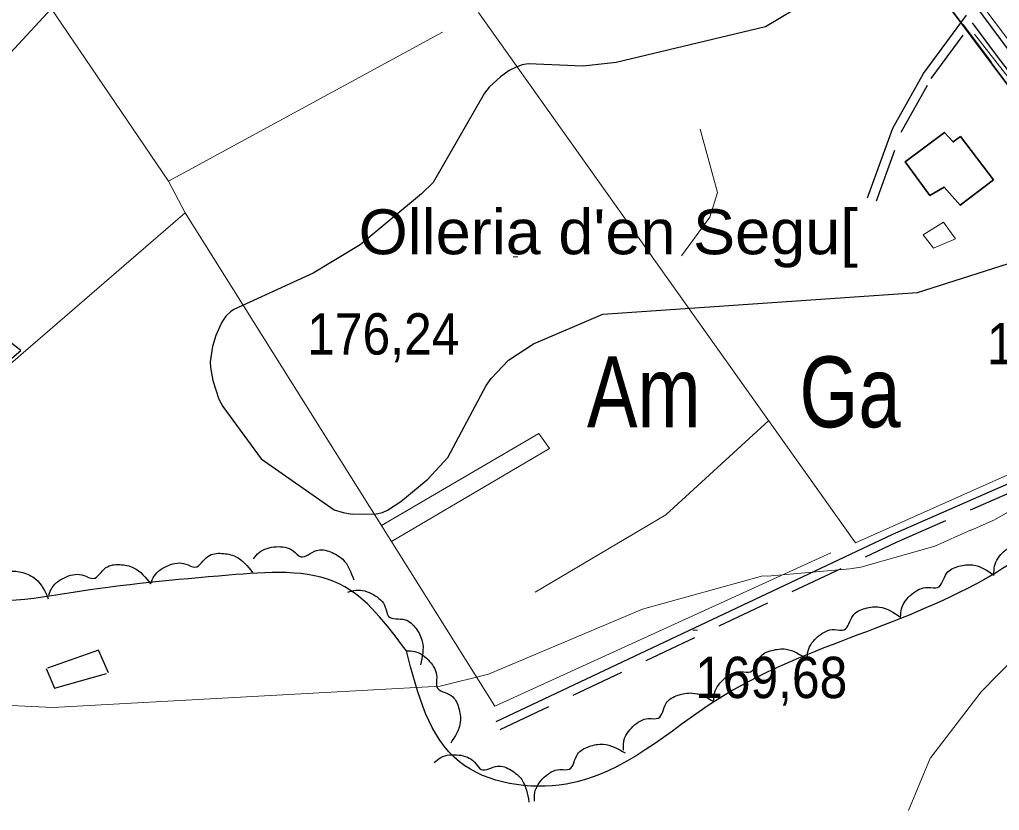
# Model space of a CAD drawing. Extents: x 480269 to 484877, y 4383588 to 4386804.
# Drawn here: x 482052.3 to 482259.6, y 4385605.8 to 4385773.1 of the extents above; entities that cross this region are included whole.
import ezdxf
from ezdxf.enums import TextEntityAlignment as Align

# ---------------------------------------------------------------- set-up
doc = ezdxf.new("R2010")
doc.units = 0
doc.header["$LTSCALE"] = 3.8
doc.linetypes.add('MEDIUM_DASHED', pattern=[4.5, 3, -1.5])
for name, color, linetype, lineweight in [('21', 7, 'Continuous', 25), ('27', 7, 'Continuous', 25), ('34', 7, 'Continuous', 35), ('38', 7, 'Continuous', 25), ('47', 7, 'Continuous', 35), ('48', 7, 'MEDIUM_DASHED', 25), ('51', 7, 'Continuous', 13), ('7', 7, 'Continuous', 13), ('8', 7, 'Continuous', 25), ('9', 7, 'Continuous', 13)]:
    doc.layers.add(name, color=color, linetype=linetype, lineweight=lineweight)
doc.layers.add('31', color=7, linetype='Continuous')
doc.layers.add('5', color=7, linetype='Continuous')

msp = doc.modelspace()

# ---------------------------------------------------------------- linework, layer by layer
at = {"layer": '21'}
msp.add_lwpolyline([(482044.36, 4385701.2), (482046.63, 4385698.12), (482052.53, 4385703.11), (482049.05, 4385705.87)], close=True, dxfattribs=at)
at = {"layer": '27'}
for points in [[(482928.34, 4385924.89), (482922.57, 4385923.15), (482885.78, 4385895.73), (482830.19, 4385870.67), (482783.99, 4385846.38), (482748.76, 4385821.32), (482700.22, 4385785.28), (482658.72, 4385739.07), (482615.66, 4385695.2), (482579.64, 4385663.09), (482560.07, 4385645.07), (482539.71, 4385649.77), (482459.85, 4385672.49), (482360.42, 4385703.82), (482306.4, 4385727.32), (482257.85, 4385789.2), (482191.3, 4385880.85), (482166.25, 4385912.96), (482169.38, 4385923.15), (482197.57, 4385932.55), (482218.71, 4385942.73), (482235.93, 4385961.53), (482260.99, 4385957.61), (482288.39, 4385973.28), (482296.22, 4385991.3), (482306.4, 4385999.91), (482324.4, 4386001.48), (482354.16, 4385995.21), (482372.16, 4385973.28), (482387.82, 4385970.15), (482414.44, 4385988.16), (482434.02, 4385990.51), (482466.12, 4385956.05), (482473.95, 4385954.08)], [(482134.14, 4385639.56), (482145.42, 4385616.05), (482167.98, 4385611.34), (482199.94, 4385629.21), (482256.34, 4385654.6), (482299.58, 4385676.23), (482309.92, 4385675.29), (482324.96, 4385660.25), (482353.16, 4385626.39), (482366.32, 4385607.58), (482355.04, 4385597.24), (482347.52, 4385585.01), (482347.52, 4385561.5), (482356.92, 4385553.04), (482382.29, 4385553.98), (482400.15, 4385553.98), (482414.25, 4385537.05), (482418.01, 4385522), (482407.67, 4385512.6), (482383.23, 4385513.54), (482370.08, 4385507.9), (482358.8, 4385494.73), (482359.74, 4385477.8), (482342.82, 4385454.29), (482257.28, 4385376.24), (482191.48, 4385317.93), (482156.7, 4385290.66), (482136.02, 4385273.73), (482119.1, 4385272.79), (482113.46, 4385285.02), (482126.62, 4385312.29), (482143.54, 4385346.14), (482160.46, 4385378.12), (482156.7, 4385395.99), (482134.14, 4385407.27), (482113.46, 4385416.68), (482093.72, 4385412.91), (482087.14, 4385401.63), (482072.1, 4385398.81), (482050.48, 4385407.27), (482035.44, 4385408.21), (482021.34, 4385395.05), (482005.36, 4385398.81), (482011, 4385429.84), (482001.6, 4385476.86), (481971.52, 4385519.18), (481936.74, 4385563.38), (481930.16, 4385579.37), (481941.44, 4385597.24), (481940.5, 4385616.99), (481916.06, 4385648.96), (481908.54, 4385674.35), (481928.28, 4385695.98), (481936.74, 4385694.1), (481957.42, 4385664.01), (481967.76, 4385648.02), (481979.04, 4385640.5), (481992.2, 4385648.02), (482008.18, 4385667.77), (482022.28, 4385668.71), (482035.44, 4385653.66), (482062.7, 4385651.78), (482096.54, 4385655.54), (482120.04, 4385653.66), (482134.14, 4385639.56)], [(482258.48, 4385655.67), (482258.61, 4385657.44), (482260.66, 4385660.63), (482264.01, 4385662.18), (482266.06, 4385662.23), (482267.83, 4385665.31), (482270.35, 4385666.91), (482273.35, 4385667.31), (482277.91, 4385665.34)], [(482101.79, 4385659.03), (482102.99, 4385660.34), (482106.58, 4385661.57), (482110.16, 4385660.7), (482111.81, 4385659.47), (482115.11, 4385660.79), (482118.08, 4385660.47), (482120.67, 4385658.92), (482123.02, 4385654.56)], [(482080.03, 4385653.72), (482080.76, 4385655.34), (482083.79, 4385657.62), (482087.47, 4385657.92), (482089.41, 4385657.26), (482092.14, 4385659.54), (482095.06, 4385660.17), (482098.01, 4385659.5), (482101.61, 4385656.09)], [(482036.86, 4385653.47), (482037.96, 4385654.86), (482041.45, 4385656.35), (482045.09, 4385655.75), (482046.82, 4385654.64), (482050.02, 4385656.19), (482053, 4385656.09), (482055.7, 4385654.74), (482058.37, 4385650.56)], [(482058.47, 4385651.31), (482059.19, 4385652.93), (482062.22, 4385655.22), (482065.9, 4385655.52), (482067.84, 4385654.86), (482070.56, 4385657.15), (482073.48, 4385657.78), (482076.43, 4385657.12), (482080.04, 4385653.71)], [(482238.74, 4385646.67), (482238.93, 4385648.44), (482241.11, 4385651.55), (482244.51, 4385652.96), (482246.57, 4385652.93), (482248.46, 4385655.94), (482251.04, 4385657.44), (482254.05, 4385657.72), (482258.53, 4385655.57)], [(482121.76, 4385651.94), (482123.48, 4385652.38), (482127.16, 4385651.45), (482129.69, 4385648.76), (482130.39, 4385646.83), (482133.88, 4385646.13), (482136.19, 4385644.24), (482137.52, 4385641.53), (482137.1, 4385636.59)], [(482218.95, 4385637.76), (482219.14, 4385639.53), (482221.32, 4385642.64), (482224.73, 4385644.05), (482226.78, 4385644.02), (482228.67, 4385647.03), (482231.26, 4385648.53), (482234.27, 4385648.81), (482238.74, 4385646.66)], [(482199.16, 4385628.86), (482199.35, 4385630.62), (482201.53, 4385633.73), (482204.94, 4385635.15), (482206.99, 4385635.12), (482208.88, 4385638.13), (482211.47, 4385639.62), (482214.48, 4385639.9), (482218.95, 4385637.76)], [(482134.14, 4385639.56), (482135.91, 4385639.41), (482139.07, 4385637.31), (482140.57, 4385633.94), (482140.59, 4385631.88), (482143.64, 4385630.07), (482145.2, 4385627.52), (482145.55, 4385624.52), (482143.52, 4385619.99)], [(482180.08, 4385618.53), (482180.14, 4385620.3), (482182.1, 4385623.55), (482185.4, 4385625.21), (482187.45, 4385625.32), (482189.12, 4385628.46), (482191.6, 4385630.13), (482194.58, 4385630.62), (482199.19, 4385628.8)], [(482161.25, 4385607.76), (482161.32, 4385609.53), (482163.29, 4385612.78), (482166.6, 4385614.41), (482168.65, 4385614.52), (482170.34, 4385617.65), (482172.82, 4385619.3), (482175.81, 4385619.78), (482180.41, 4385617.94)], [(482140.04, 4385615.9), (482141.46, 4385616.96), (482145.21, 4385617.5), (482148.58, 4385615.98), (482149.96, 4385614.46), (482153.45, 4385615.14), (482156.31, 4385614.28), (482158.57, 4385612.28), (482160.07, 4385607.55)]]:
    msp.add_spline(points, degree=3, dxfattribs=at)
at = {"layer": '34'}
msp.add_line((482251.88, 4385772.09), (482257.87, 4385764.09), dxfattribs=at)
msp.add_lwpolyline([(481732.67, 4386453.74), (481770, 4386403), (482108, 4385964), (482722, 4385145)], dxfattribs=at)
at = {"layer": '38'}
for points in [[(481964.71, 4386161.53), (481984.04, 4386137.62), (482003.54, 4386111.27), (482025.11, 4386083.66), (482045.74, 4386055.24), (482069.87, 4386023.53), (482092.3, 4385993.28), (482108.78, 4385971.62), (482137.33, 4385933.4), (482160.69, 4385901.12), (482191.72, 4385858.66), (482221.47, 4385819.56), (482242.16, 4385792.86), (482263.36, 4385764.29), (482272.97, 4385751.53), (482292.17, 4385726.65), (482297.56, 4385719.51), (482298.68, 4385719.01), (482300.35, 4385718.99), (482305.15, 4385718.26), (482309.51, 4385716.64)], [(482231.76, 4385735.43), (482237.09, 4385750.13), (482243.56, 4385761.69), (482252.65, 4385774.08)], [(482253.87, 4385772.44), (482259.37, 4385765.04), (482270.86, 4385750.05), (482288.86, 4385726.29), (482295.69, 4385717.31), (482296.78, 4385716.83)], [(482153.18, 4385624.57), (482237.11, 4385664.26), (482310.39, 4385696.34), (482310.52, 4385696.96), (482309.92, 4385698.86), (482296.78, 4385716.83)]]:
    msp.add_lwpolyline(points, dxfattribs=at)
at = {"layer": '38', "linetype": 'MEDIUM_DASHED'}
for points in [[(482233.6, 4385734.76), (482238.88, 4385749.31), (482245.21, 4385760.63), (482253.87, 4385772.44)], [(482153.98, 4385622.88), (482237.89, 4385662.56), (482311.25, 4385694.68)]]:
    msp.add_lwpolyline(points, dxfattribs=at)
at = {"layer": '47'}
msp.add_lwpolyline([(482258.42, 4385739.23), (482251.37, 4385733.85), (482247.94, 4385737.68), (482244.93, 4385735.89), (482239.71, 4385743.03), (482248, 4385749.24), (482249.82, 4385747.25), (482251.38, 4385748.38)], close=True, dxfattribs=at)
at = {"layer": '47', "lineweight": 13}
msp.add_lwpolyline([(482250.35, 4385726.74), (482247.81, 4385730.24), (482243.51, 4385727.59), (482245.69, 4385724.76)], close=True, dxfattribs=at)
at = {"layer": '48'}
msp.add_lwpolyline([(482071.13, 4385634.87), (482068.97, 4385639.66), (482057.92, 4385635.81), (482059.7, 4385631.64)], close=True, dxfattribs=at)
at = {"layer": '51'}
msp.add_line((482083.8, 4385738.92), (482039.24, 4385804.6), dxfattribs=at)
for points in [[(482779.62, 4386098.45), (482742.85, 4386070.07), (482699.48, 4386036.34), (482644.98, 4385992.23), (482611.45, 4385965.76), (482554.45, 4385920.69), (482472.77, 4385856.39), (482299.35, 4385719.82), (482274.18, 4385752.03), (482255.92, 4385776.25), (482234.75, 4385804.89), (482209.61, 4385837.32), (482152.61, 4385914.04), (482157.42, 4385920.91)], [(482149.4, 4385774.65), (482229.21, 4385662.41), (482307.44, 4385697.3), (482307.88, 4385699.78), (482270.82, 4385749), (482254.38, 4385770.06)], [(482141.76, 4385770.45), (482083.8, 4385738.92), (482087.33, 4385732.24)], [(482196.28, 4385749.97), (482200.01, 4385736.56), (482198.39, 4385731.29), (482192.34, 4385723.17)], [(482029.1, 4385681.95), (482087.33, 4385732.24), (482152.87, 4385627.8), (482223.94, 4385660.26)], [(482161.37, 4385651.94), (482189.08, 4385668.34), (482210.83, 4385688.28)], [(482130.97, 4385662.71), (482164.45, 4385682.34), (482162.19, 4385685.56), (482128.86, 4385666.08)]]:
    msp.add_lwpolyline(points, dxfattribs=at)
at = {"layer": '7'}
for p, q in [((482156.74, 4385722.95), (482157.74, 4385722.95)), ((482194.74, 4385643.91), (482195.74, 4385643.91))]:
    msp.add_line(p, q, dxfattribs=at)
at = {"layer": '8'}
msp.add_lwpolyline([(482252.53, 4385796.92), (482210.17, 4385771.58), (482178.54, 4385764.06), (482171.56, 4385763.24), (482159.93, 4385763.77), (482158.63, 4385763.53), (482157.38, 4385763.09), (482155.91, 4385762.33), (482154.08, 4385761.05), (482151.66, 4385758.81), (482150.67, 4385757.58), (482139.8, 4385738.69), (482137.36, 4385736.23), (482124.34, 4385725.43), (482114.43, 4385719.44), (482097.64, 4385711.8), (482096.95, 4385711.3), (482095.97, 4385710.37), (482095.36, 4385709.55), (482095.02, 4385708.97), (482093.79, 4385706.25), (482093.11, 4385703.94), (482092.62, 4385700.71), (482092.68, 4385699.49), (482093.2, 4385696.75), (482094.43, 4385692.81), (482095.33, 4385691.25), (482103.44, 4385680.18), (482118.85, 4385669.38), (482120.74, 4385668.79), (482122.68, 4385668.49), (482127.77, 4385668.54), (482129.09, 4385668.8), (482130.17, 4385669.31), (482132.95, 4385671.14), (482138.66, 4385675.89), (482142.89, 4385680.49), (482151, 4385695.71), (482152.07, 4385697.17), (482155.73, 4385701.07), (482161.08, 4385704.5), (482175.73, 4385710.77), (482242.28, 4385715.39), (482283.7, 4385728.59)], dxfattribs=at)
at = {"layer": '9'}
for points in [[(482050.32, 4385766.05), (482059.94, 4385776.5)], [(482261.43, 4385668.86), (482258.61, 4385667.28), (482253.66, 4385665.09), (482253.5, 4385665.07), (482245.95, 4385661.71), (482230.32, 4385657.23), (482227.99, 4385656.87), (482210.55, 4385655.34), (482209.58, 4385655.41), (482184.14, 4385648.39), (482151.54, 4385634.63), (482141.27, 4385632.1), (482059.33, 4385627.54), (482047.38, 4385628.14)], [(482240.39, 4385605.75), (482245.05, 4385616.95), (482245.11, 4385616.98), (482255.81, 4385630.87), (482263.13, 4385638.36)]]:
    msp.add_lwpolyline(points, dxfattribs=at)

# ---------------------------------------------------------------- texts
at = {"layer": '31', "width": 0.8}
for s, p in [('Ga', (482228.03, 4385686.85)), ('Am', (482184.4, 4385686.85))]:
    msp.add_text(s, height=15, dxfattribs=at).set_placement(p, align=Align.CENTER)
at = {"layer": '5', "width": 1.05}
msp.add_text("Olleria d'en Segu[", height=9.5, dxfattribs=at).set_placement((482124.05, 4385723.47))
at = {"layer": '7', "width": 0.9}
for s, p in [('176,24', (482113.15, 4385702.24)), ('174,47', (482256.98, 4385700.18)), ('169,68', (482195.24, 4385629.54))]:
    msp.add_text(s, height=8.75, dxfattribs=at).set_placement(p)

doc.saveas('drawing.dxf')
